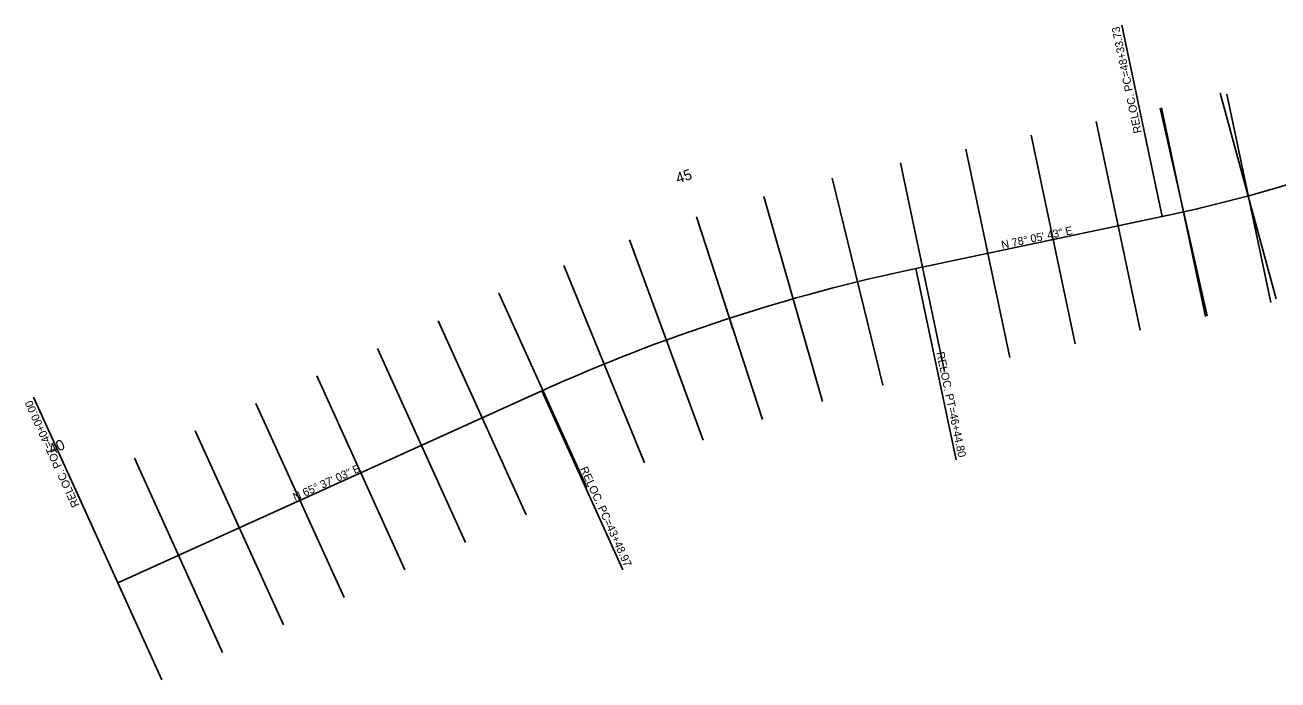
# Model space of a CAD drawing. Extents: x 1965757 to 1970272, y 1117058 to 1118406.
# Drawn here: x 1965757 to 1966697, y 1117058 to 1117550 of the extents above; entities that cross this region are included whole.
import ezdxf

# ---------------------------------------------------------------- set-up
doc = ezdxf.new("R2010")
doc.units = 0
for name, color, linetype in [('RD_HC_CL_Rel', 7, 'Continuous'), ('RD_HC_Data_Rel', 7, 'Continuous'), ('RD_HC_Data_Tic_Rel', 7, 'Continuous'), ('RD_HC_TX_Rel_Sta50', 7, 'Continuous'), ('RD_PD_PatLn1', 7, 'Continuous'), ('RD_PD_PatLn2', 7, 'Continuous')]:
    doc.layers.add(name, color=color, linetype=linetype)

msp = doc.modelspace()

# ---------------------------------------------------------------- linework, layer by layer
at = {"layer": 'RD_HC_CL_Rel'}
for p, q in [((1966425.26, 1117367.21), (1966610.12, 1117406.19)), ((1965826.85, 1117131.21), (1966144.7, 1117275.28))]:
    msp.add_line(p, q, dxfattribs=at)
for centre, radius, start, end in [((1966373.74, 1118527.46), 1145.91, 281.90472, 295.04633), ((1966705.48, 1116038.04), 1358.39, 101.90472, 114.38256)]:
    msp.add_arc(centre, radius, start, end, dxfattribs=at)
at = {"layer": 'RD_HC_Data_Rel'}
for p, q in [((1966610.12, 1117406.19), (1966579.81, 1117549.97)), ((1966425.26, 1117367.21), (1966455.55, 1117223.56)), ((1966144.7, 1117275.28), (1966205.51, 1117141.11)), ((1965826.85, 1117131.21), (1965763.61, 1117270.73))]:
    msp.add_line(p, q, dxfattribs=at)
at = {"layer": 'RD_HC_Data_Tic_Rel'}
for p, q in [((1966674.54, 1117421.73), (1966673.49, 1117425.59)), ((1966577.12, 1117399.23), (1966576.3, 1117403.14)), ((1966479.28, 1117378.6), (1966478.45, 1117382.52)), ((1966381.59, 1117357.25), (1966380.63, 1117361.14)), ((1966285.44, 1117329.86), (1966282.96, 1117337.46)), ((1966285.44, 1117329.86), (1966287.91, 1117322.25)), ((1966191.56, 1117295.46), (1966190.05, 1117299.17)), ((1966100.09, 1117255.06), (1966098.44, 1117258.7)), ((1966009.01, 1117213.78), (1966007.36, 1117217.42)), ((1965917.93, 1117172.49), (1965916.28, 1117176.14)), ((1965826.85, 1117131.21), (1965823.55, 1117138.5)), ((1965826.85, 1117131.21), (1965830.15, 1117123.92))]:
    msp.add_line(p, q, dxfattribs=at)
at = {"layer": 'RD_PD_PatLn1'}
for p, q in [((1966658.47, 1117498.14), (1966691.48, 1117341.58)), ((1966609.55, 1117487.82), (1966642.55, 1117331.27)), ((1966560.62, 1117477.51), (1966593.63, 1117320.95)), ((1966511.7, 1117467.2), (1966544.7, 1117310.64)), ((1966462.77, 1117456.88), (1966495.78, 1117300.32)), ((1966413.85, 1117446.57), (1966446.85, 1117290.01)), ((1966362.51, 1117434.94), (1966400.66, 1117279.56)), ((1966311.34, 1117421.38), (1966355.18, 1117267.5)), ((1966260.7, 1117405.94), (1966310.17, 1117253.78)), ((1966210.66, 1117388.64), (1966265.7, 1117238.41)), ((1966161.29, 1117369.52), (1966221.83, 1117221.41)), ((1966112.66, 1117348.59), (1966178.61, 1117202.81)), ((1966067.07, 1117327.92), (1966133.12, 1117182.19)), ((1966021.53, 1117307.28), (1966087.58, 1117161.55)), ((1965975.99, 1117286.64), (1966042.04, 1117140.91)), ((1965930.45, 1117266), (1965996.5, 1117120.27)), ((1965884.91, 1117245.36), (1965950.96, 1117099.63)), ((1965839.37, 1117224.72), (1965905.42, 1117078.99)), ((1965793.83, 1117204.08), (1965859.88, 1117058.35))]:
    msp.add_line(p, q, dxfattribs=at)
at = {"layer": 'RD_PD_PatLn2'}
for p, q in [((1966653.54, 1117498.92), (1966695.54, 1117344.53)), ((1966608.41, 1117487.69), (1966643.64, 1117331.62)), ((1966560.62, 1117477.51), (1966593.63, 1117320.95)), ((1966511.7, 1117467.2), (1966544.7, 1117310.64)), ((1966462.77, 1117456.88), (1966495.78, 1117300.32)), ((1966413.85, 1117446.57), (1966446.85, 1117290.01)), ((1966362.51, 1117434.94), (1966400.66, 1117279.56)), ((1966311.34, 1117421.38), (1966355.18, 1117267.5)), ((1966260.7, 1117405.94), (1966310.17, 1117253.78)), ((1966210.66, 1117388.64), (1966265.7, 1117238.41)), ((1966161.29, 1117369.52), (1966221.83, 1117221.41)), ((1966112.66, 1117348.59), (1966178.61, 1117202.81)), ((1966067.07, 1117327.92), (1966133.12, 1117182.19)), ((1966021.53, 1117307.28), (1966087.58, 1117161.55)), ((1965975.99, 1117286.64), (1966042.04, 1117140.91)), ((1965930.45, 1117266), (1965996.5, 1117120.27)), ((1965884.91, 1117245.36), (1965950.96, 1117099.63)), ((1965839.37, 1117224.72), (1965905.42, 1117078.99)), ((1965793.83, 1117204.08), (1965859.88, 1117058.35))]:
    msp.add_line(p, q, dxfattribs=at)

# ---------------------------------------------------------------- texts
at = {"layer": 'RD_HC_Data_Rel'}
for s, rotation, p in [('RELOC. PC=48+33.73', 101.90472, (1966594.76, 1117469.38)), ('N 78%%d 05\' 43" E', 11.90472, (1966490.04, 1117381.89)), ('RELOC. PT=46+44.80', 281.90472, (1966440.63, 1117304.03)), ('RELOC. POT=40+00.00', 114.38256, (1965798.2, 1117189.59)), ('N 65%%d 37\' 03" E', 24.38256, (1965959.82, 1117192.58)), ('RELOC. PC=43+48.97', 294.38256, (1966173.35, 1117216.9))]:
    msp.add_text(s, height=6, rotation=rotation, dxfattribs=at).set_placement(p)
at = {"layer": 'RD_HC_TX_Rel_Sta50'}
for s, rotation, p in [('45', 18.01224, (1966246.84, 1117430.87)), ('40', 24.38256, (1965777.14, 1117227.25))]:
    msp.add_text(s, height=8, rotation=rotation, dxfattribs=at).set_placement(p)

doc.saveas('drawing.dxf')
